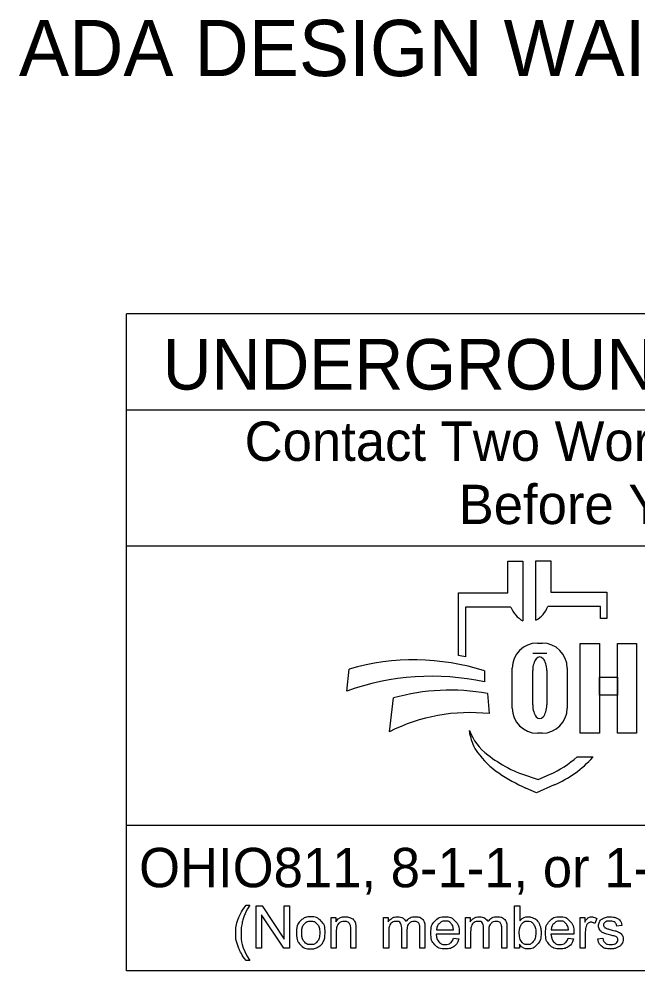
# Model space of a CAD drawing. Extents: x -15 to 405, y -40 to 87.
# Drawn here: x 54.151 to 56.352, y -38.144 to -34.758 of the extents above; entities that cross this region are included whole.
import ezdxf

# ---------------------------------------------------------------- set-up
doc = ezdxf.new("R2010")
doc.units = 0
doc.layers.add('GM_X_Adjacent_County', color=7, linetype='Continuous')
doc.layers.add('GM_X_Township', color=7, linetype='Continuous')

msp = doc.modelspace()

# ---------------------------------------------------------------- linework, layer by layer
at = {"layer": 'GM_X_Adjacent_County'}
for p, q in [((55.8893, -36.7984), (55.8893, -36.6869)), ((55.8893, -36.6869), (55.9429, -36.6869)), ((55.9429, -36.6869), (55.9429, -36.899)), ((55.9886, -36.8966), (55.9886, -36.6846)), ((55.9886, -36.6846), (56.0422, -36.6846)), ((56.0422, -36.6846), (56.0422, -36.7961)), ((55.7133, -37.0223), (55.7133, -36.7984)), ((55.7133, -36.7984), (55.8893, -36.7984)), ((56.0422, -36.7961), (56.2415, -36.7961)), ((56.2415, -36.7961), (56.2415, -36.8899)), ((55.7386, -36.8498), (55.7386, -37.0267)), ((55.8997, -36.8498), (55.7386, -36.8498)), ((56.2182, -36.8475), (56.0318, -36.8475)), ((56.2182, -36.8899), (56.2182, -36.8475)), ((56.2415, -36.8899), (56.2182, -36.8899)), ((55.9943, -36.9776), (56.0108, -36.9776)), ((56.0275, -37.0146), (55.9777, -37.0146)), ((55.316, -37.1486), (55.3253, -37.0704)), ((55.9048, -37.209), (55.9048, -37.067)), ((56.1003, -37.067), (56.1003, -37.209)), ((55.8066, -37.0769), (55.8066, -37.1158)), ((55.9777, -37.1977), (55.9777, -37.0753)), ((56.0275, -37.0753), (56.0275, -37.1977)), ((55.4678, -37.2931), (55.4825, -37.173)), ((55.8166, -37.1575), (55.8228, -37.2285)), ((55.7555, -37.306), (55.7524, -37.2881)), ((56.0108, -37.2985), (55.9943, -37.2985)), ((56.1358, -37.3819), (56.1932, -37.3819)), ((55.9373, -37.4423), (55.9968, -37.4627)), ((55.9968, -37.4627), (56.0378, -37.4449)), ((55.9907, -37.5098), (55.9534, -37.4933)), ((56.054, -37.4823), (55.9907, -37.5098))]:
    msp.add_line(p, q, dxfattribs=at)
for points in [[(56.1467, -36.9786), (56.2147, -36.9786), (56.2147, -37.2986), (56.1467, -37.2986)], [(56.2789, -36.9786), (56.3468, -36.9786), (56.3468, -37.2986), (56.2789, -37.2986)], [(56.2147, -37.0985), (56.2789, -37.0985), (56.2789, -37.1625), (56.2147, -37.1625)]]:
    msp.add_lwpolyline(points, close=True, dxfattribs=at)
for points in [[(54.9579, -37.9101), (54.971, -37.9101)], [(54.9946, -38.0628), (54.9946, -37.9126), (55.0149, -37.9126), (55.0939, -38.0305), (55.0939, -37.9126), (55.1129, -37.9126), (55.1129, -38.0628), (55.0926, -38.0628), (55.0136, -37.9448), (55.0136, -38.0628), (54.9946, -38.0628)], [(55.9301, -38.0628), (55.913, -38.0628), (55.913, -37.9126), (55.9314, -37.9126), (55.9314, -37.9661)], [(55.2606, -38.0628), (55.2606, -37.9539), (55.2772, -37.9539), (55.2772, -37.9694)], [(55.447, -38.0628), (55.447, -37.9539), (55.4635, -37.9539), (55.4635, -37.9693)], [(55.7384, -38.0628), (55.7384, -37.9539), (55.7548, -37.9539), (55.7548, -37.9693)], [(56.1461, -38.0628), (56.1461, -37.9539), (56.1627, -37.9539), (56.1627, -37.9704)], [(55.5945, -37.9881), (55.5945, -38.0628), (55.5761, -38.0628), (55.5761, -37.9943)], [(55.8859, -37.9881), (55.8859, -38.0628), (55.8675, -38.0628), (55.8675, -37.9943)], [(56.2052, -37.9574), (56.1987, -37.9745)], [(56.2951, -37.9821), (56.2771, -37.9845)], [(55.279, -38.0034), (55.279, -38.0628), (55.2606, -38.0628)], [(55.3489, -37.9959), (55.3489, -38.0628), (55.3305, -38.0628), (55.3305, -37.9966)], [(55.4654, -38.0063), (55.4654, -38.0628), (55.447, -38.0628)], [(55.5301, -37.9996), (55.5301, -38.0628), (55.5116, -38.0628), (55.5116, -37.9921)], [(55.7157, -38.0131), (55.6346, -38.0131)], [(55.6356, -37.998), (55.6964, -37.998)], [(55.7568, -38.0063), (55.7568, -38.0628), (55.7384, -38.0628)], [(55.8214, -37.9996), (55.8214, -38.0628), (55.803, -38.0628), (55.803, -37.9921)], [(56.1237, -38.0131), (56.0426, -38.0131)], [(56.0436, -37.998), (56.1044, -37.998)], [(56.1646, -38.0058), (56.1646, -38.0628), (56.1461, -38.0628)], [(55.6962, -38.0276), (55.7152, -38.03)], [(55.9301, -38.0491), (55.9301, -38.0628)], [(56.1042, -38.0276), (56.1232, -38.03)], [(56.2087, -38.0302), (56.2269, -38.0274)], [(54.971, -38.1069), (54.9579, -38.1069)]]:
    msp.add_lwpolyline(points, dxfattribs=at)
for centre, radius, start, end in [((55.991, -36.813), 0.0985, 201.9296, 240.7469), ((55.9405, -36.8107), 0.0985, 299.2531, 338.0704), ((55.9943, -37.067), 0.0895, 90, 180), ((56.0108, -37.067), 0.0895, 0, 90), ((55.5554, -37.8565), 0.8191, 72.1402, 106.3144), ((55.5852, -37.8312), 0.8191, 79.2074, 81.0007), ((55.6185, -37.9876), 0.8919, 77.8238, 109.8274), ((55.6824, -37.8773), 0.7322, 79.44, 105.8467), ((55.9943, -37.209), 0.0895, 180, 270), ((56.0108, -37.209), 0.0895, 270, 0), ((55.7544, -37.8605), 0.6357, 83.8248, 116.8021), ((55.9398, -37.216), 0.2008, 201.0457, 232.5314), ((55.8968, -37.2819), 0.1433, 189.6817, 216.0884), ((56.0305, -37.1845), 0.3088, 216.0884, 235.7167), ((56.1324, -36.9648), 0.5173, 232.5314, 241.794), ((55.8944, -37.1145), 0.3602, 293.4582, 312.0712), ((55.8944, -37.1145), 0.401, 293.4582, 317.8286), ((56.197, -36.9402), 0.6044, 235.7167, 246.2325), ((56.0472, -37.1236), 0.3371, 241.794, 250.9821)]:
    msp.add_arc(centre, radius, start, end, dxfattribs=at)
for centre, start_param, end_param in [((56.0026, -37.0753), 4.712389, 7.853982), ((56.0026, -37.1977), 1.570796, 4.712389)]:
    msp.add_ellipse(centre, major_axis=(0, 0.0484), ratio=0.514403, start_param=start_param, end_param=end_param, dxfattribs=at)
for points in [[(54.9579, -38.1069), (54.9426, -38.0877), (54.932, -38.0619), (54.9215, -38.0361), (54.9215, -38.0084), (54.9215, -37.984), (54.9294, -37.9617), (54.9386, -37.9358), (54.9579, -37.9101)], [(54.971, -37.9101), (54.9587, -37.9314), (54.9547, -37.9405), (54.9485, -37.9546), (54.9449, -37.97), (54.9405, -37.9891), (54.9405, -38.0085), (54.9405, -38.0578), (54.971, -38.1069)], [(55.1371, -38.0083), (55.1371, -37.9781), (55.1539, -37.9636), (55.1679, -37.9515), (55.1881, -37.9515), (55.2105, -37.9515), (55.2247, -37.9662), (55.2389, -37.9809), (55.2389, -38.0068), (55.2389, -38.0278), (55.2327, -38.0398), (55.2264, -38.0518), (55.2143, -38.0585), (55.2023, -38.0652), (55.1881, -38.0652), (55.1652, -38.0652), (55.1512, -38.0505), (55.1371, -38.0359), (55.1371, -38.0083)], [(55.2772, -37.9694), (55.2891, -37.9515), (55.3118, -37.9515), (55.3216, -37.9515), (55.3298, -37.955), (55.3381, -37.9586), (55.3422, -37.9643), (55.3463, -37.9701), (55.3479, -37.9779), (55.3489, -37.9831), (55.3489, -37.9959)], [(55.4635, -37.9693), (55.4686, -37.9613), (55.4771, -37.9564), (55.4856, -37.9515), (55.4965, -37.9515), (55.5086, -37.9515), (55.5163, -37.9565), (55.524, -37.9616), (55.5272, -37.9706), (55.5401, -37.9515), (55.5609, -37.9515), (55.5771, -37.9515), (55.5858, -37.9605), (55.5945, -37.9694), (55.5945, -37.9881)], [(55.7152, -38.03), (55.7107, -38.0467), (55.6985, -38.0559), (55.6863, -38.0652), (55.6674, -38.0652), (55.6435, -38.0652), (55.6296, -38.0505), (55.6156, -38.0358), (55.6156, -38.0093), (55.6156, -37.9818), (55.6297, -37.9667), (55.6438, -37.9515), (55.6664, -37.9515), (55.6882, -37.9515), (55.702, -37.9664), (55.7158, -37.9812), (55.7158, -38.0082), (55.7158, -38.0098), (55.7157, -38.0131)], [(55.7548, -37.9693), (55.76, -37.9613), (55.7685, -37.9564), (55.777, -37.9515), (55.7878, -37.9515), (55.7999, -37.9515), (55.8077, -37.9565), (55.8154, -37.9616), (55.8186, -37.9706), (55.8315, -37.9515), (55.8522, -37.9515), (55.8684, -37.9515), (55.8772, -37.9605), (55.8859, -37.9694), (55.8859, -37.9881)], [(55.9314, -37.9661), (55.9431, -37.9515), (55.9612, -37.9515), (55.9713, -37.9515), (55.9802, -37.9556), (55.9892, -37.9596), (55.995, -37.9669), (56.0008, -37.9742), (56.004, -37.9846), (56.0073, -37.9949), (56.0073, -38.0067), (56.0073, -38.0346), (55.9935, -38.0499), (55.9797, -38.0652), (55.9603, -38.0652), (55.941, -38.0652), (55.9301, -38.0491)], [(56.1232, -38.03), (56.1187, -38.0467), (56.1065, -38.0559), (56.0943, -38.0652), (56.0754, -38.0652), (56.0515, -38.0652), (56.0376, -38.0505), (56.0236, -38.0358), (56.0236, -38.0093), (56.0236, -37.9818), (56.0377, -37.9667), (56.0518, -37.9515), (56.0744, -37.9515), (56.0962, -37.9515), (56.11, -37.9664), (56.1238, -37.9812), (56.1238, -38.0082), (56.1238, -38.0098), (56.1237, -38.0131)], [(56.1627, -37.9704), (56.1691, -37.9589), (56.1745, -37.9552), (56.1798, -37.9515), (56.1863, -37.9515), (56.1956, -37.9515), (56.2052, -37.9574)], [(56.2269, -38.0274), (56.2285, -38.0384), (56.2355, -38.0442), (56.2426, -38.05), (56.2552, -38.05), (56.2679, -38.05), (56.2741, -38.0449), (56.2803, -38.0397), (56.2803, -38.0327), (56.2803, -38.0265), (56.2748, -38.0229), (56.271, -38.0204), (56.2559, -38.0166), (56.2356, -38.0115), (56.2278, -38.0078), (56.2199, -38.004), (56.2159, -37.9974), (56.2118, -37.9908), (56.2118, -37.9828), (56.2118, -37.9756), (56.2152, -37.9694), (56.2185, -37.9632), (56.2242, -37.9591), (56.2286, -37.9559), (56.236, -37.9537), (56.2434, -37.9515), (56.252, -37.9515), (56.2648, -37.9515), (56.2745, -37.9552), (56.2842, -37.9589), (56.2888, -37.9652), (56.2934, -37.9715), (56.2951, -37.9821)], [(55.1561, -38.0083), (55.1561, -38.0292), (55.1652, -38.0396), (55.1743, -38.05), (55.1881, -38.05), (55.2018, -38.05), (55.2109, -38.0396), (55.22, -38.0291), (55.22, -38.0077), (55.22, -37.9875), (55.2108, -37.9771), (55.2017, -37.9667), (55.1881, -37.9667), (55.1743, -37.9667), (55.1652, -37.9771), (55.1561, -37.9874), (55.1561, -38.0083)], [(55.3305, -37.9966), (55.3305, -37.9854), (55.3284, -37.9798), (55.3262, -37.9742), (55.3207, -37.9709), (55.3152, -37.9675), (55.3079, -37.9675), (55.2961, -37.9675), (55.2876, -37.975), (55.279, -37.9825), (55.279, -38.0034)], [(55.5116, -37.9921), (55.5116, -37.9798), (55.5071, -37.9737), (55.5026, -37.9675), (55.4924, -37.9675), (55.4846, -37.9675), (55.478, -37.9716), (55.4714, -37.9757), (55.4684, -37.9836), (55.4654, -37.9915), (55.4654, -38.0063)], [(55.5761, -37.9943), (55.5761, -37.9832), (55.5743, -37.9783), (55.5725, -37.9735), (55.5678, -37.9705), (55.5631, -37.9675), (55.5567, -37.9675), (55.5452, -37.9675), (55.5377, -37.9752), (55.5301, -37.9828), (55.5301, -37.9996)], [(55.6964, -37.998), (55.6951, -37.9842), (55.6894, -37.9773), (55.6806, -37.9666), (55.6666, -37.9666), (55.6539, -37.9666), (55.6452, -37.9752), (55.6365, -37.9837), (55.6356, -37.998)], [(55.803, -37.9921), (55.803, -37.9798), (55.7985, -37.9737), (55.794, -37.9675), (55.7837, -37.9675), (55.776, -37.9675), (55.7693, -37.9716), (55.7627, -37.9757), (55.7598, -37.9836), (55.7568, -37.9915), (55.7568, -38.0063)], [(55.8675, -37.9943), (55.8675, -37.9832), (55.8657, -37.9783), (55.8639, -37.9735), (55.8592, -37.9705), (55.8544, -37.9675), (55.8481, -37.9675), (55.8366, -37.9675), (55.829, -37.9752), (55.8214, -37.9828), (55.8214, -37.9996)], [(55.9298, -38.0075), (55.9298, -38.0271), (55.9352, -38.0358), (55.9439, -38.05), (55.9587, -38.05), (55.9707, -38.05), (55.9795, -38.0395), (55.9883, -38.029), (55.9883, -38.0082), (55.9883, -37.9869), (55.9799, -37.9768), (55.9715, -37.9666), (55.9595, -37.9666), (55.9474, -37.9666), (55.9386, -37.9771), (55.9298, -37.9876), (55.9298, -38.0075)], [(56.1044, -37.998), (56.1031, -37.9842), (56.0974, -37.9773), (56.0886, -37.9666), (56.0745, -37.9666), (56.0618, -37.9666), (56.0532, -37.9752), (56.0445, -37.9837), (56.0436, -37.998)], [(56.1987, -37.9745), (56.192, -37.9705), (56.1853, -37.9705), (56.1793, -37.9705), (56.1745, -37.9741), (56.1697, -37.9778), (56.1676, -37.9842), (56.1646, -37.9941), (56.1646, -38.0058)], [(56.2771, -37.9845), (56.2758, -37.9761), (56.2699, -37.9713), (56.264, -37.9666), (56.2533, -37.9666), (56.2406, -37.9666), (56.2351, -37.9708), (56.2297, -37.975), (56.2297, -37.9807), (56.2297, -37.9843), (56.2319, -37.9871), (56.2342, -37.9901), (56.239, -37.9921), (56.2418, -37.9931), (56.2553, -37.9968), (56.2749, -38.002), (56.2827, -38.0053), (56.2904, -38.0087), (56.2948, -38.015), (56.2993, -38.0213), (56.2993, -38.0308), (56.2993, -38.04), (56.2939, -38.0481), (56.2885, -38.0562), (56.2783, -38.0607), (56.2682, -38.0652), (56.2553, -38.0652), (56.2341, -38.0652), (56.223, -38.0564), (56.2118, -38.0475), (56.2087, -38.0302)], [(55.6346, -38.0131), (55.6356, -38.031), (55.6447, -38.0405), (55.6538, -38.05), (55.6675, -38.05), (55.6776, -38.05), (55.6848, -38.0447), (55.692, -38.0393), (55.6962, -38.0276)], [(56.0426, -38.0131), (56.0436, -38.031), (56.0527, -38.0405), (56.0618, -38.05), (56.0755, -38.05), (56.0856, -38.05), (56.0928, -38.0447), (56.1, -38.0393), (56.1042, -38.0276)]]:
    msp.add_open_spline(points, degree=3, dxfattribs=at)
at = {"layer": 'GM_X_Township'}
for p, q in [((54.5333, -38.1439), (54.5333, -35.8064)), ((58.7833, -35.8064), (54.5333, -35.8064)), ((54.5333, -36.148), (58.7833, -36.148)), ((54.5333, -36.6313), (58.7833, -36.6313)), ((58.7833, -37.626), (54.5333, -37.626)), ((58.7833, -38.1439), (54.5333, -38.1439))]:
    msp.add_line(p, q, dxfattribs=at)

# ---------------------------------------------------------------- texts
at = {"layer": 'GM_X_Adjacent_County'}
for s, height, p in [('ADA DESIGN WAIVERS', 0.2, (54.1502, -34.9611)), ('UNDERGROUND UTILITIES', 0.18, (54.6614, -36.076)), ('Contact Two Working Days', 0.14, (54.9529, -36.3295)), ('Before You Dig', 0.14, (55.7141, -36.5545)), ('OHIO811, 8-1-1, or 1-800-362-2764', 0.14, (54.5777, -37.8461))]:
    msp.add_text(s, height=height, dxfattribs=at).set_placement(p)

doc.saveas('drawing.dxf')
